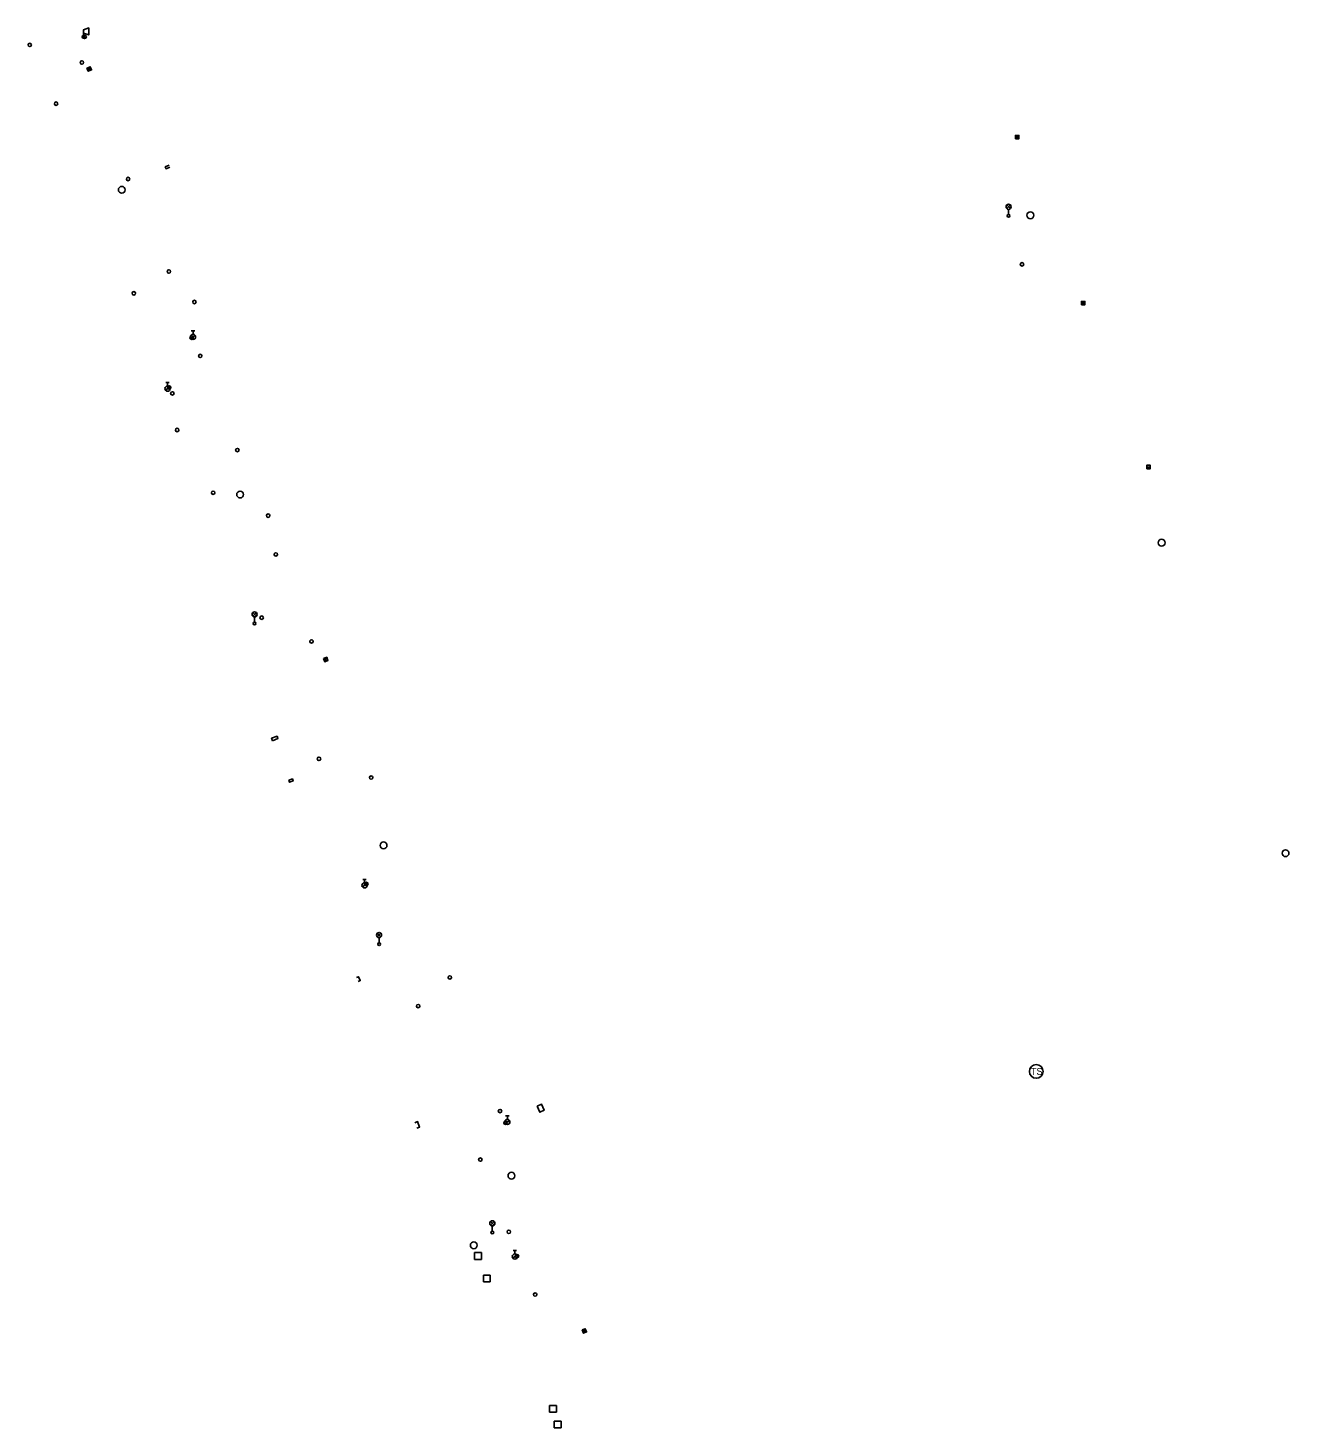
# Model space of a CAD drawing. Extents: x -577028 to -568584, y -1207664 to -1202947.
# Drawn here: x -575022.4 to -574838.7, y -1204821.1 to -1204617.1 of the extents above; entities that cross this region are included whole.
import ezdxf

# ---------------------------------------------------------------- set-up
doc = ezdxf.new("R2010")
doc.units = 0
doc.layers.add('CIZÍ_NADZEM', color=7, linetype='Continuous')
doc.layers.add('ELE_EON', color=7, linetype='Continuous')

msp = doc.modelspace()

# ---------------------------------------------------------------- linework, layer by layer
at = {"layer": 'CIZÍ_NADZEM'}
for p, q in [((-575013.58, -1204622.88), (-575013.4, -1204623.34)), ((-574878.56, -1204633.04), (-574878.06, -1204633.04)), ((-574879.82, -1204643.45), (-574879.3, -1204642.92)), ((-574879.29, -1204643.45), (-574879.82, -1204642.92)), ((-574879.56, -1204643.56), (-574879.56, -1204644.31)), ((-574868.95, -1204657.22), (-574868.45, -1204657.22)), ((-574998.66, -1204662.38), (-574998.07, -1204661.92)), ((-574998.62, -1204661.28), (-574998.12, -1204661.28)), ((-574998.37, -1204661.78), (-574998.37, -1204661.28)), ((-575002.33, -1204668.81), (-575001.83, -1204668.81)), ((-575002.08, -1204669.31), (-575002.08, -1204668.81)), ((-575002.37, -1204669.92), (-575001.78, -1204669.46)), ((-574859.43, -1204681.11), (-574858.93, -1204681.11)), ((-574989.66, -1204702.86), (-574989.14, -1204702.33)), ((-574989.13, -1204702.85), (-574989.66, -1204702.33)), ((-574989.4, -1204702.97), (-574989.4, -1204703.72)), ((-574979.13, -1204708.93), (-574978.95, -1204709.39)), ((-574973.67, -1204742.3), (-574973.08, -1204741.84)), ((-574973.63, -1204741.2), (-574973.13, -1204741.2)), ((-574973.38, -1204741.7), (-574973.38, -1204741.2)), ((-574971.53, -1204749.58), (-574971.01, -1204749.05)), ((-574971, -1204749.57), (-574971.53, -1204749.05)), ((-574971.27, -1204749.69), (-574971.27, -1204750.44)), ((-574952.87, -1204776.77), (-574952.28, -1204776.31)), ((-574952.83, -1204775.67), (-574952.33, -1204775.67)), ((-574952.58, -1204776.17), (-574952.58, -1204775.67)), ((-574955.03, -1204791.59), (-574954.51, -1204791.06)), ((-574954.5, -1204791.58), (-574955.03, -1204791.06)), ((-574954.77, -1204791.7), (-574954.77, -1204792.45)), ((-574951.73, -1204795.28), (-574951.23, -1204795.28)), ((-574951.48, -1204795.78), (-574951.48, -1204795.28)), ((-574956.35, -1204795.58), (-574957.35, -1204795.58)), ((-574957.35, -1204795.58), (-574957.35, -1204796.58)), ((-574957.35, -1204796.58), (-574956.35, -1204796.58)), ((-574956.35, -1204796.58), (-574956.35, -1204795.58)), ((-574951.77, -1204796.39), (-574951.18, -1204795.93)), ((-574955.06, -1204798.86), (-574956.06, -1204798.86)), ((-574956.06, -1204798.86), (-574956.06, -1204799.86)), ((-574955.06, -1204799.86), (-574955.06, -1204798.86)), ((-574956.06, -1204799.86), (-574955.06, -1204799.86)), ((-574941.45, -1204806.77), (-574941.27, -1204807.23)), ((-574945.44, -1204817.85), (-574946.44, -1204817.85)), ((-574946.44, -1204817.85), (-574946.44, -1204818.85)), ((-574945.44, -1204818.85), (-574945.44, -1204817.85)), ((-574946.44, -1204818.85), (-574945.44, -1204818.85)), ((-574944.74, -1204820.14), (-574945.74, -1204820.14)), ((-574945.74, -1204820.14), (-574945.74, -1204821.14)), ((-574945.74, -1204821.14), (-574944.74, -1204821.14)), ((-574944.74, -1204821.14), (-574944.74, -1204820.14))]:
    msp.add_line(p, q, dxfattribs=at)
for points in [[(-575014.32, -1204618.44), (-575014.32, -1204617.39), (-575013.57, -1204617.14), (-575013.57, -1204618.14), (-575014.32, -1204617.89)], [(-575001.75, -1204637.43), (-575002.3, -1204637.65), (-575002.41, -1204637.37), (-575001.87, -1204637.15)], [(-574986.79, -1204720.99), (-574986, -1204720.69), (-574986.13, -1204720.34), (-574986.92, -1204720.64), (-574986.79, -1204720.99)], [(-574984.41, -1204726.74), (-574983.9, -1204726.55), (-574983.79, -1204726.85), (-574984.3, -1204727.04), (-574984.41, -1204726.74)], [(-574974.56, -1204755.52), (-574974.24, -1204755.39), (-574974, -1204755.94), (-574974.33, -1204756.07)], [(-574948.24, -1204774.23), (-574947.87, -1204775.12), (-574947.22, -1204774.85), (-574947.6, -1204773.96), (-574948.24, -1204774.23)], [(-574966.07, -1204776.65), (-574965.66, -1204776.49), (-574965.36, -1204777.29), (-574965.76, -1204777.45)]]:
    msp.add_lwpolyline(points, dxfattribs=at)
for points in [[(-575013.82, -1204622.97), (-575013.63, -1204623.44), (-575013.16, -1204623.25), (-575013.35, -1204622.79)], [(-574878.56, -1204633.29), (-574878.06, -1204633.29), (-574878.06, -1204632.79), (-574878.56, -1204632.79)], [(-574868.95, -1204657.47), (-574868.45, -1204657.47), (-574868.45, -1204656.97), (-574868.95, -1204656.97)], [(-574859.43, -1204681.36), (-574858.93, -1204681.36), (-574858.93, -1204680.86), (-574859.43, -1204680.86)], [(-574979.37, -1204709.02), (-574979.18, -1204709.49), (-574978.71, -1204709.3), (-574978.9, -1204708.83)], [(-574941.69, -1204806.86), (-574941.5, -1204807.33), (-574941.03, -1204807.14), (-574941.22, -1204806.67)]]:
    msp.add_lwpolyline(points, close=True, dxfattribs=at)
for centre, radius in [((-575022.16, -1204619.6), 0.25), ((-575014.32, -1204618.44), 0.2), ((-575014.16, -1204618.44), 0.25), ((-575014.56, -1204622.17), 0.25), ((-575018.32, -1204628.17), 0.25), ((-575008.75, -1204640.72), 0.5), ((-575007.83, -1204639.15), 0.25), ((-574879.56, -1204643.19), 0.375), ((-574879.56, -1204644.51), 0.2), ((-574876.38, -1204644.43), 0.5), ((-575001.88, -1204652.62), 0.25), ((-574877.6, -1204651.58), 0.25), ((-575007, -1204655.8), 0.25), ((-574998.17, -1204657.06), 0.25), ((-574998.58, -1204662.27), 0.25), ((-574998.37, -1204662.15), 0.375), ((-574997.32, -1204664.92), 0.25), ((-575002.08, -1204669.69), 0.375), ((-575001.83, -1204669.52), 0.25), ((-575001.38, -1204670.39), 0.25), ((-575000.68, -1204675.72), 0.25), ((-574991.91, -1204678.64), 0.25), ((-574995.44, -1204684.86), 0.25), ((-574991.51, -1204685.12), 0.5), ((-574987.43, -1204688.2), 0.25), ((-574857.27, -1204692.14), 0.5), ((-574986.31, -1204693.85), 0.25), ((-574989.4, -1204702.59), 0.375), ((-574988.37, -1204703.07), 0.25), ((-574989.4, -1204703.92), 0.2), ((-574981.11, -1204706.52), 0.25), ((-574980.02, -1204723.63), 0.25), ((-574972.42, -1204726.36), 0.25), ((-574970.62, -1204736.24), 0.5), ((-574839.21, -1204737.38), 0.5), ((-574973.38, -1204742.07), 0.375), ((-574973.12, -1204741.87), 0.25), ((-574971.27, -1204749.31), 0.375), ((-574971.27, -1204750.64), 0.2), ((-574960.96, -1204755.48), 0.25), ((-574965.57, -1204759.66), 0.25), ((-574953.65, -1204774.96), 0.25), ((-574952.86, -1204776.66), 0.25), ((-574952.58, -1204776.54), 0.375), ((-574956.51, -1204782.03), 0.25), ((-574951.98, -1204784.38), 0.5), ((-574954.77, -1204791.32), 0.375), ((-574954.77, -1204792.65), 0.2), ((-574952.37, -1204792.55), 0.25), ((-574957.47, -1204794.52), 0.5), ((-574951.48, -1204796.16), 0.375), ((-574951.18, -1204796.09), 0.25), ((-574948.53, -1204801.7), 0.25)]:
    msp.add_circle(centre, radius, dxfattribs=at)
at = {"layer": 'ELE_EON'}
msp.add_circle((-574875.53, -1204769.18), 1, dxfattribs=at)

# ---------------------------------------------------------------- texts
msp.add_text('TS', height=1, dxfattribs=at).set_placement((-574876.32, -1204769.68))

doc.saveas('drawing.dxf')
